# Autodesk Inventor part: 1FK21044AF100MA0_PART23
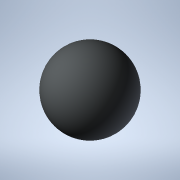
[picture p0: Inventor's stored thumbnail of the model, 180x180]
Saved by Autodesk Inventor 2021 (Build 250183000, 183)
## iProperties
Created: 2025-04
Part Number: 1FK21044AF100MA0_PART23
Material: Generic
Catalog Web Link: www.3dfindit.com
Description: -Servo synchronous motor
Document SubType Name: Modeling
Designer: psAdmin
Mass: 0.137258 g
Surface Area: 1.2868 cm^2
Volume: 0.137258 cm^3
Density: 1 g/cm^3
Appearance: PSOLRGB-212-217-219
Category: PARTsolutions
Title: 1FK21044AF100MA0_PART23
Author: Cadenas PARTsolutions
Comments: Servo synchronous motor
Sending System: PARTsolutions
Preprocessor: ST-DEVELOPER v19.3
PSOL_IDENT_0: {$CADENAS_DATA/23d-libs/siemens_ag/_cat_/ec/e4/1fk21044af100ma0.prj},216 {VTYP=3D},{NB=1FK21044AF100
PSOL_IDENT_1: MA0_PART23},{LINA=1FK21044AF100MA0_PART23},{NN=1FK21044AF100MA0_PART23},{NOPRJ=TRUE},{DATE=19.08.202
PSOL_IDENT_2: 5 14:01:05},{GEOMDATE=30.07.2025 02:01:01},{VERSION=},{LINEID=10},{WBVAR=},{WBNUMERIC=}  {NB=1FK2104
PSOL_IDENT_3: 4AF100MA0_PART23},{LINA=1FK21044AF100MA0_PART23},{KT=DUMMY},{PREVIEW=../../../_pool_/cb/72/p_d211_xx
PSOL_IDENT_4: _00434j.png},{DESCSHORT=SIMOTICS S-1FK2 HD, SINAMICS S210 3AC 400V-480V, 1.27 Nm, 3000 rpm},{DESCLON
PSOL_IDENT_5: G=SIMOTICS S-1FK2 HD servo motor M0=1.27 Nm; PN = 0.4 kW at nN=3000 rpm (380-480 V); PN = 0.2 kW at
PSOL_IDENT_6: nN=1500 rpm (200-240 V); with holding brake; degree of protection IP64; cylindrical shaft D19x40mm;
PSOL_IDENT_7: absolute encoder 22-bit + 12-bit multiturn (encoder AM22DQC); with OCC interface; plug size M17, rot
PSOL_IDENT_8: atable; SIMOTICS S-1FK2 servomotorfor a wide range of uses in industrial environments. SIMOTICS S‑1F
PSOL_IDENT_9: K2 servomotors are compact synchronous motors with a high dynamic performance that set themselves ap
PSOL_IDENT_10: art as a result of their high power density, degree of protection and overload capability. The motor
PSOL_IDENT_11: s are available in two variants: as High Dynamic variant (highest dynamic performance as a result of
PSOL_IDENT_12: the low intrinsic moment of inertia for applications demanding a high dynamic performance with low
PSOL_IDENT_13: moved masses) - and as Compact variant (precise and stable closed-loop control for medium up to larg
PSOL_IDENT_14: e moved masses as a result of a medium intrinsic moment of inertia). SIMOTICSS‑1FK2 servomotors full
PSOL_IDENT_15: y exploit their strengths in a system with the SINAMICSS210 frequency converter and simple connectio
PSOL_IDENT_16: n using the one cable connection (OCC). Advantages include the short control and positioning times,
PSOL_IDENT_17: fast and precise correction of disturbing quantities as well as stable control with a high dynamic p
PSOL_IDENT_18: erformance. The servo motors can be configured to address a wide range of requirements. For example
PSOL_IDENT_19: with and without holding brake, IP64 or IP65 degree of protection, singleturn or multiturn absolute
PSOL_IDENT_20: encoders - to name just a few. Further, the servomotors are available in different shaft heights ext
PSOL_IDENT_21: ending from 20 to 100. A shaft sealing ring is available to achieve an IP65 degree of protection and
PSOL_IDENT_22: for subsequent mounting at the motor or as spare part. SIMOTICS - the optimum motor for each and ev
PSOL_IDENT_23: ery motion control application.},{INTNO=195125043275},{SUPPLIERALTNO=1FK2104-4AF10-0MA0},{MANUID=1FK
PSOL_IDENT_24: 21044AF100MA0},{MANUNAME=Siemens},{MANUTYPEDESC=Synchronous motor 1FK2-HD 1.27 NM},{AAU732=SIMOTICS}
PSOL_IDENT_25: ,{AAO057=S-1FK2},{AAU734=SIMOTICS S-1FK2 HD servo motor M0=1.27 Nm; PN = 0.4 kW at nN=3000 rpm (380-
PSOL_IDENT_26: 480 V); PN = 0.2 kW at nN=1500 rpm (200-240 V); with holding brake; degree of protection IP64; cylin
PSOL_IDENT_27: drical shaft D19x40mm; absolute encoder 22-bit + 12-bit multiturn (encoder AM22DQC); with OCC interf
PSOL_IDENT_28: ace; plug size M17, rotatable;},{AAW338=Synchronous motor 1FK2-HD 1.27 NM},{AAO742=SIMOTICS},{AAO663=
PSOL_IDENT_29: 4042948694015},{NOCUPEROU=1},{PRICEQUANTITY=1},{QUANTITYMIN=1},{QUANTITYINT=1},{CTN=85015100},{COO=D
PSOL_IDENT_30: E},{AAO676=1FK2104-4AF10-0MA0},{AAO677=Siemens AG},{ORDERUNIT=C62},{CONTENTUNIT=C62}
NB: 1FK21044AF100MA0_PART23
NT: Servo synchronous motor
NBSYN: $MANUID._PART23
LINA: 1FK21044AF100MA0_PART23
CATALOG: SIEMENS
PREVIEW: ../../../_pool_/cb/72/p_d211_xx_00434j.png
DESCSHORT: SIMOTICS S-1FK2 HD, SINAMICS S210 3AC 400V-480V, 1.27 Nm, 3000 rpm
DESCLONG: SIMOTICS S-1FK2 HD servo motor M0=1.27 Nm; PN = 0.4 kW at nN=3000 rpm (380-480 V); PN = 0.2 kW at nN=1500 rpm (200-240 V); with holding brake; degree of protect
INTNO: 195125043275
SUPPLIERALTNO: 1FK2104-4AF10-0MA0
MANUID: 1FK21044AF100MA0
MANUNAME: Siemens
MANUTYPEDESC: Synchronous motor 1FK2-HD 1.27 NM
AAU732: SIMOTICS
AAO057: S-1FK2
AAU734: SIMOTICS S-1FK2 HD servo motor M0=1.27 Nm; PN = 0.4 kW at nN=3000 rpm (380-480 V); PN = 0.2 kW at nN=1500 rpm (200-240 V); with holding brake; degree of protect
AAW338: Synchronous motor 1FK2-HD 1.27 NM
AAO742: SIMOTICS
AAO663: 4042948694015.0
NOCUPEROU: 1
PRICEQUANTITY: 1
QUANTITYMIN: 1
QUANTITYINT: 1
CTN: 85015100
COO: DE
ARTICLENO: 1FK21044AF100MA0_PART23
BOMINFO: 1FK21044AF100MA0_PART23
CREATOR: CADENAS GmbH
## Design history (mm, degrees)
feature "2025_04_17_15_33_01_0673"
body "Solid1"
